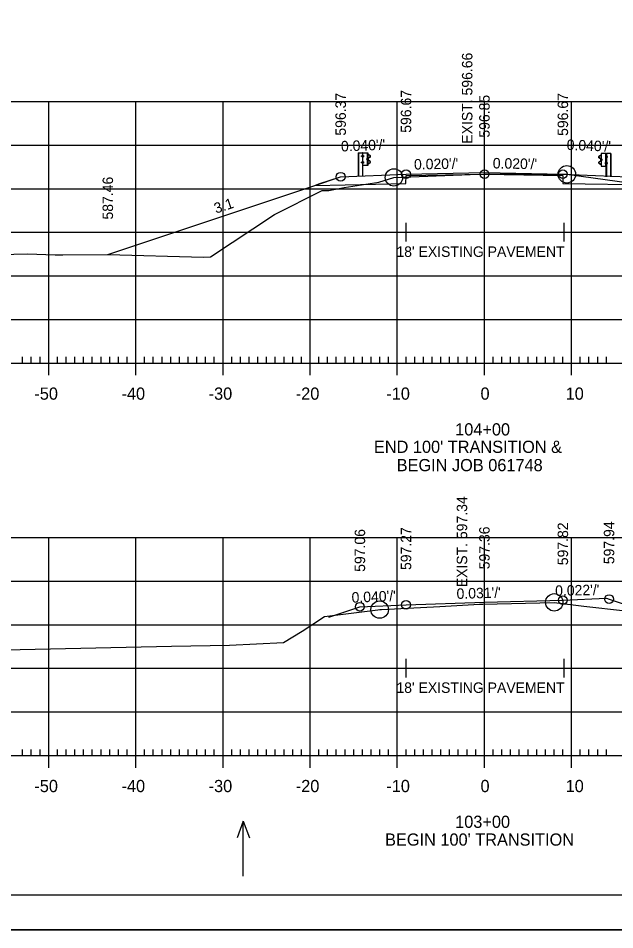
# Model space of a CAD drawing. Extents: x 961436 to 1372525, y 380079 to 2027791.
# Drawn here: x 1370137 to 1370205.5, y 380109.1 to 380213.6 of the extents above; entities that cross this region are included whole.
import ezdxf

# ---------------------------------------------------------------- set-up
doc = ezdxf.new("R2010")
doc.units = 0
for name, color, linetype in [('R_Alt Surface', 7, 'Continuous'), ('R_Axis', 7, 'Continuous'), ('R_Axis Annot', 7, 'Continuous'), ('R_Drive', 7, 'Continuous'), ('R_Exist Surface', 7, 'Continuous'), ('R_Fin Surface', 7, 'Continuous'), ('R_Fin Surface Annot', 7, 'Continuous'), ('R_Grid', 7, 'Continuous'), ('R_No Plot', 7, 'Continuous'), ('R_Proposed Road', 7, 'Continuous'), ('R_Water Annot', 7, 'Continuous'), ('R_Xsect Elev', 7, 'Continuous')]:
    doc.layers.add(name, color=color, linetype=linetype)

msp = doc.modelspace()

# ---------------------------------------------------------------- linework, layer by layer
at = {"layer": 'R_Alt Surface'}
msp.add_lwpolyline([(1370171.03, 380194.44), (1370181.49, 380194.65), (1370181.5, 380195.56), (1370190.5, 380195.74), (1370199.5, 380195.56), (1370199.51, 380194.65), (1370209.77, 380194.51)], dxfattribs=at)
at = {"layer": 'R_Axis'}
for p, q in [((1370137.5, 380174.06), (1370137.5, 380174.76)), ((1370138.5, 380174.06), (1370138.5, 380174.76)), ((1370139.5, 380174.06), (1370139.5, 380174.76)), ((1370140.5, 380172.66), (1370140.5, 380175.46)), ((1370141.5, 380174.06), (1370141.5, 380174.76)), ((1370142.5, 380174.06), (1370142.5, 380174.76)), ((1370143.5, 380174.06), (1370143.5, 380174.76)), ((1370144.5, 380174.06), (1370144.5, 380174.76)), ((1370145.5, 380174.06), (1370145.5, 380174.76)), ((1370146.5, 380174.06), (1370146.5, 380174.76)), ((1370147.5, 380174.06), (1370147.5, 380174.76)), ((1370148.5, 380174.06), (1370148.5, 380174.76)), ((1370149.5, 380174.06), (1370149.5, 380174.76)), ((1370150.5, 380172.66), (1370150.5, 380175.46)), ((1370151.5, 380174.06), (1370151.5, 380174.76)), ((1370152.5, 380174.06), (1370152.5, 380174.76)), ((1370153.5, 380174.06), (1370153.5, 380174.76)), ((1370154.5, 380174.06), (1370154.5, 380174.76)), ((1370155.5, 380174.06), (1370155.5, 380174.76)), ((1370156.5, 380174.06), (1370156.5, 380174.76)), ((1370157.5, 380174.06), (1370157.5, 380174.76)), ((1370158.5, 380174.06), (1370158.5, 380174.76)), ((1370159.5, 380174.06), (1370159.5, 380174.76)), ((1370160.5, 380172.66), (1370160.5, 380175.46)), ((1370161.5, 380174.06), (1370161.5, 380174.76)), ((1370162.5, 380174.06), (1370162.5, 380174.76)), ((1370163.5, 380174.06), (1370163.5, 380174.76)), ((1370164.5, 380174.06), (1370164.5, 380174.76)), ((1370165.5, 380174.06), (1370165.5, 380174.76)), ((1370166.5, 380174.06), (1370166.5, 380174.76)), ((1370167.5, 380174.06), (1370167.5, 380174.76)), ((1370168.5, 380174.06), (1370168.5, 380174.76)), ((1370169.5, 380174.06), (1370169.5, 380174.76)), ((1370170.5, 380172.66), (1370170.5, 380175.46)), ((1370171.5, 380174.06), (1370171.5, 380174.76)), ((1370172.5, 380174.06), (1370172.5, 380174.76)), ((1370173.5, 380174.06), (1370173.5, 380174.76)), ((1370174.5, 380174.06), (1370174.5, 380174.76)), ((1370175.5, 380174.06), (1370175.5, 380174.76)), ((1370176.5, 380174.06), (1370176.5, 380174.76)), ((1370177.5, 380174.06), (1370177.5, 380174.76)), ((1370178.5, 380174.06), (1370178.5, 380174.76)), ((1370179.5, 380174.06), (1370179.5, 380174.76)), ((1370180.5, 380172.66), (1370180.5, 380175.46)), ((1370181.5, 380174.06), (1370181.5, 380174.76)), ((1370182.5, 380174.06), (1370182.5, 380174.76)), ((1370183.5, 380174.06), (1370183.5, 380174.76)), ((1370184.5, 380174.06), (1370184.5, 380174.76)), ((1370185.5, 380174.06), (1370185.5, 380174.76)), ((1370186.5, 380174.06), (1370186.5, 380174.76)), ((1370187.5, 380174.06), (1370187.5, 380174.76)), ((1370188.5, 380174.06), (1370188.5, 380174.76)), ((1370189.5, 380174.06), (1370189.5, 380174.76)), ((1370190.5, 380172.66), (1370190.5, 380175.46)), ((1370191.5, 380174.06), (1370191.5, 380174.76)), ((1370192.5, 380174.06), (1370192.5, 380174.76)), ((1370193.5, 380174.06), (1370193.5, 380174.76)), ((1370194.5, 380174.06), (1370194.5, 380174.76)), ((1370195.5, 380174.06), (1370195.5, 380174.76)), ((1370196.5, 380174.06), (1370196.5, 380174.76)), ((1370197.5, 380174.06), (1370197.5, 380174.76)), ((1370198.5, 380174.06), (1370198.5, 380174.76)), ((1370199.5, 380174.06), (1370199.5, 380174.76)), ((1370200.5, 380172.66), (1370200.5, 380175.46)), ((1370201.5, 380174.06), (1370201.5, 380174.76)), ((1370202.5, 380174.06), (1370202.5, 380174.76)), ((1370203.5, 380174.06), (1370203.5, 380174.76)), ((1370204.5, 380174.06), (1370204.5, 380174.76)), ((1370050.5, 380174.06), (1370330.5, 380174.06)), ((1370137.5, 380129.06), (1370137.5, 380129.76)), ((1370138.5, 380129.06), (1370138.5, 380129.76)), ((1370139.5, 380129.06), (1370139.5, 380129.76)), ((1370140.5, 380127.66), (1370140.5, 380130.46)), ((1370141.5, 380129.06), (1370141.5, 380129.76)), ((1370142.5, 380129.06), (1370142.5, 380129.76)), ((1370143.5, 380129.06), (1370143.5, 380129.76)), ((1370144.5, 380129.06), (1370144.5, 380129.76)), ((1370145.5, 380129.06), (1370145.5, 380129.76)), ((1370146.5, 380129.06), (1370146.5, 380129.76)), ((1370147.5, 380129.06), (1370147.5, 380129.76)), ((1370148.5, 380129.06), (1370148.5, 380129.76)), ((1370149.5, 380129.06), (1370149.5, 380129.76)), ((1370150.5, 380127.66), (1370150.5, 380130.46)), ((1370151.5, 380129.06), (1370151.5, 380129.76)), ((1370152.5, 380129.06), (1370152.5, 380129.76)), ((1370153.5, 380129.06), (1370153.5, 380129.76)), ((1370154.5, 380129.06), (1370154.5, 380129.76)), ((1370155.5, 380129.06), (1370155.5, 380129.76)), ((1370156.5, 380129.06), (1370156.5, 380129.76)), ((1370157.5, 380129.06), (1370157.5, 380129.76)), ((1370158.5, 380129.06), (1370158.5, 380129.76)), ((1370159.5, 380129.06), (1370159.5, 380129.76)), ((1370160.5, 380127.66), (1370160.5, 380130.46)), ((1370161.5, 380129.06), (1370161.5, 380129.76)), ((1370162.5, 380129.06), (1370162.5, 380129.76)), ((1370163.5, 380129.06), (1370163.5, 380129.76)), ((1370164.5, 380129.06), (1370164.5, 380129.76)), ((1370165.5, 380129.06), (1370165.5, 380129.76)), ((1370166.5, 380129.06), (1370166.5, 380129.76)), ((1370167.5, 380129.06), (1370167.5, 380129.76)), ((1370168.5, 380129.06), (1370168.5, 380129.76)), ((1370169.5, 380129.06), (1370169.5, 380129.76)), ((1370170.5, 380127.66), (1370170.5, 380130.46)), ((1370171.5, 380129.06), (1370171.5, 380129.76)), ((1370172.5, 380129.06), (1370172.5, 380129.76)), ((1370173.5, 380129.06), (1370173.5, 380129.76)), ((1370174.5, 380129.06), (1370174.5, 380129.76)), ((1370175.5, 380129.06), (1370175.5, 380129.76)), ((1370176.5, 380129.06), (1370176.5, 380129.76)), ((1370177.5, 380129.06), (1370177.5, 380129.76)), ((1370178.5, 380129.06), (1370178.5, 380129.76)), ((1370179.5, 380129.06), (1370179.5, 380129.76)), ((1370180.5, 380127.66), (1370180.5, 380130.46)), ((1370181.5, 380129.06), (1370181.5, 380129.76)), ((1370182.5, 380129.06), (1370182.5, 380129.76)), ((1370183.5, 380129.06), (1370183.5, 380129.76)), ((1370184.5, 380129.06), (1370184.5, 380129.76)), ((1370185.5, 380129.06), (1370185.5, 380129.76)), ((1370186.5, 380129.06), (1370186.5, 380129.76)), ((1370187.5, 380129.06), (1370187.5, 380129.76)), ((1370188.5, 380129.06), (1370188.5, 380129.76)), ((1370189.5, 380129.06), (1370189.5, 380129.76)), ((1370190.5, 380127.66), (1370190.5, 380130.46)), ((1370191.5, 380129.06), (1370191.5, 380129.76)), ((1370192.5, 380129.06), (1370192.5, 380129.76)), ((1370193.5, 380129.06), (1370193.5, 380129.76)), ((1370194.5, 380129.06), (1370194.5, 380129.76)), ((1370195.5, 380129.06), (1370195.5, 380129.76)), ((1370196.5, 380129.06), (1370196.5, 380129.76)), ((1370197.5, 380129.06), (1370197.5, 380129.76)), ((1370198.5, 380129.06), (1370198.5, 380129.76)), ((1370199.5, 380129.06), (1370199.5, 380129.76)), ((1370200.5, 380127.66), (1370200.5, 380130.46)), ((1370201.5, 380129.06), (1370201.5, 380129.76)), ((1370202.5, 380129.06), (1370202.5, 380129.76)), ((1370203.5, 380129.06), (1370203.5, 380129.76)), ((1370204.5, 380129.06), (1370204.5, 380129.76)), ((1370050.5, 380129.06), (1370330.5, 380129.06))]:
    msp.add_line(p, q, dxfattribs=at)
at = {"layer": 'R_Drive'}
for p, q in [((1370181.49, 380190.13), (1370181.49, 380187.99)), ((1370199.62, 380190.13), (1370199.62, 380187.99)), ((1370181.49, 380189.06), (1370199.62, 380189.06)), ((1370181.49, 380140.13), (1370181.49, 380137.99)), ((1370199.62, 380140.13), (1370199.62, 380137.99)), ((1370181.49, 380139.06), (1370199.62, 380139.06))]:
    msp.add_line(p, q, dxfattribs=at)
at = {"layer": 'R_Exist Surface'}
for points in [[(1370127.01, 380186.32), (1370138.08, 380186.58), (1370141.22, 380186.47), (1370142.1, 380186.48), (1370147.29, 380186.52), (1370158.27, 380186.21), (1370159.05, 380186.26), (1370166.4, 380191.1), (1370171.89, 380193.84), (1370172.66, 380193.85), (1370174.4, 380194.18), (1370178.39, 380194.81), (1370180.11, 380195.35), (1370188.85, 380195.68), (1370190.52, 380195.72), (1370192.53, 380195.71), (1370199.96, 380195.71), (1370207.39, 380194.68)], [(1370129.95, 380141.09), (1370137.23, 380141.23), (1370154.6, 380141.59), (1370161.26, 380141.72), (1370167.44, 380142.01), (1370169.57, 380143.3), (1370172.15, 380145.01), (1370178.27, 380145.76), (1370178.48, 380145.79), (1370178.67, 380145.8), (1370185.4, 380146.16), (1370189.92, 380146.4), (1370190.32, 380146.41), (1370198.51, 380146.62), (1370201.9, 380146.2), (1370206.68, 380145.66), (1370207.43, 380145.38), (1370211.52, 380143.3), (1370217.62, 380140), (1370218.51, 380139.85), (1370218.93, 380139.84), (1370221.76, 380139.76), (1370248.2, 380139.15)]]:
    msp.add_lwpolyline(points, dxfattribs=at)
at = {"layer": 'R_Fin Surface'}
for points in [[(1370147.28, 380186.52), (1370171.03, 380194.44), (1370174, 380195.43), (1370181.5, 380195.73), (1370190.5, 380195.91), (1370199.5, 380195.73), (1370207, 380195.43), (1370209.77, 380194.51), (1370220.89, 380190.81), (1370235.05, 380186.08)], [(1370147.28, 380186.52), (1370171.03, 380194.44), (1370171.5, 380194.6), (1370174, 380195.43), (1370181.5, 380195.73), (1370190.5, 380195.91), (1370199.5, 380195.73), (1370207, 380195.43), (1370209.5, 380194.6), (1370209.98, 380194.44), (1370232.55, 380186.91), (1370235.05, 380186.08)], [(1370172.66, 380144.93), (1370173.32, 380145.15), (1370175.5, 380145.88), (1370176.21, 380146.12), (1370181.5, 380146.33), (1370190.5, 380146.65), (1370199.5, 380146.88), (1370204.5, 380147.09), (1370204.8, 380147), (1370208.95, 380145.61), (1370208.96, 380145.61), (1370213, 380144.27), (1370217.25, 380142.85), (1370226.86, 380139.64)]]:
    msp.add_lwpolyline(points, dxfattribs=at)
at = {"layer": 'R_Grid'}
for p, q in [((1370050.5, 380204.06), (1370330.5, 380204.06)), ((1370140.5, 380174.06), (1370140.5, 380204.06)), ((1370150.5, 380174.06), (1370150.5, 380204.06)), ((1370160.5, 380174.06), (1370160.5, 380204.06)), ((1370170.5, 380174.06), (1370170.5, 380204.06)), ((1370180.5, 380174.06), (1370180.5, 380204.06)), ((1370190.5, 380174.06), (1370190.5, 380204.06)), ((1370200.5, 380174.06), (1370200.5, 380204.06)), ((1370050.5, 380199.06), (1370330.5, 380199.06)), ((1370050.5, 380194.06), (1370330.5, 380194.06)), ((1370050.5, 380189.06), (1370330.5, 380189.06)), ((1370050.5, 380184.06), (1370330.5, 380184.06)), ((1370050.5, 380179.06), (1370330.5, 380179.06)), ((1370050.5, 380174.06), (1370330.5, 380174.06)), ((1370050.5, 380154.06), (1370330.5, 380154.06)), ((1370140.5, 380129.06), (1370140.5, 380154.06)), ((1370150.5, 380129.06), (1370150.5, 380154.06)), ((1370160.5, 380129.06), (1370160.5, 380154.06)), ((1370170.5, 380129.06), (1370170.5, 380154.06)), ((1370180.5, 380129.06), (1370180.5, 380154.06)), ((1370190.5, 380129.06), (1370190.5, 380154.06)), ((1370200.5, 380129.06), (1370200.5, 380154.06)), ((1370050.5, 380149.06), (1370330.5, 380149.06)), ((1370050.5, 380144.06), (1370330.5, 380144.06)), ((1370050.5, 380139.06), (1370330.5, 380139.06)), ((1370050.5, 380134.06), (1370330.5, 380134.06)), ((1370050.5, 380129.06), (1370330.5, 380129.06))]:
    msp.add_line(p, q, dxfattribs=at)
at = {"layer": 'R_No Plot'}
for p, q in [((1370348.68, 380113.06), (1370032.5, 380113.06)), ((1370020.1, 380109.08), (1370353.44, 380109.08))]:
    msp.add_line(p, q, dxfattribs=at)
for points in [[(1370020.1, 380322.41), (1370353.44, 380322.41), (1370353.44, 380109.08), (1370020.1, 380109.08)], [(1370266.42, 380318.52), (1370286.04, 380318.52), (1370286.04, 380308.64), (1370302.16, 380308.64), (1370325.36, 380308.64), (1370325.48, 380280.48), (1370348.68, 380280.48), (1370348.68, 380113.06), (1370032.5, 380113.06), (1370032.5, 380318.52)]]:
    msp.add_lwpolyline(points, close=True, dxfattribs=at)
for centre, radius in [((1370199.96, 380195.71), 1), ((1370174, 380195.43), 0.5), ((1370180.11, 380195.35), 1), ((1370181.5, 380195.73), 0.5), ((1370190.52, 380195.72), 0.5), ((1370199.5, 380195.73), 0.5), ((1370198.51, 380146.62), 1), ((1370199.5, 380146.88), 0.5), ((1370204.8, 380147), 0.5), ((1370176.21, 380146.12), 0.5), ((1370178.48, 380145.79), 1), ((1370181.5, 380146.33), 0.5)]:
    msp.add_circle(centre, radius, dxfattribs=at)
at = {"layer": 'R_Proposed Road'}
for p, q in [((1370176, 380198.18), (1370176, 380195.51)), ((1370176.04, 380198.18), (1370176.04, 380195.51)), ((1370176.43, 380197.74), (1370176.43, 380197.84)), ((1370176.49, 380197.73), (1370176.43, 380197.73)), ((1370176.49, 380197.86), (1370176.44, 380197.86)), ((1370176.49, 380197.83), (1370176.44, 380197.83)), ((1370176.49, 380197.76), (1370176.44, 380197.76)), ((1370176.49, 380197.76), (1370176.44, 380197.76)), ((1370176.56, 380198.18), (1370176.49, 380198.18)), ((1370176.49, 380197.73), (1370176.49, 380197.86)), ((1370176.53, 380195.51), (1370176.53, 380198.18)), ((1370176.56, 380198.18), (1370176.56, 380198.18)), ((1370176.62, 380197.79), (1370176.56, 380197.79)), ((1370176.57, 380197.85), (1370176.62, 380197.85)), ((1370176.57, 380197.72), (1370176.62, 380197.72)), ((1370176.62, 380197.85), (1370176.62, 380197.72)), ((1370177.02, 380197.4), (1370177.02, 380197.5)), ((1370177.08, 380197.52), (1370177.03, 380197.52)), ((1370177.08, 380197.39), (1370177.08, 380197.52)), ((1370177.09, 380196.73), (1370177.09, 380198.17)), ((1370177.24, 380197.95), (1370177.13, 380198.02)), ((1370177.23, 380197.93), (1370177.13, 380197.99)), ((1370177.13, 380197.39), (1370177.14, 380197.53)), ((1370177.16, 380197.39), (1370177.16, 380197.53)), ((1370177.18, 380197.6), (1370177.37, 380197.71)), ((1370177.2, 380197.58), (1370177.38, 380197.69)), ((1370177.37, 380197.82), (1370177.23, 380197.93)), ((1370177.38, 380197.84), (1370177.24, 380197.95)), ((1370203.63, 380197.76), (1370203.76, 380197.87)), ((1370203.81, 380197.5), (1370203.63, 380197.61)), ((1370203.64, 380197.74), (1370203.78, 380197.85)), ((1370203.83, 380197.52), (1370203.64, 380197.63)), ((1370203.76, 380197.87), (1370203.88, 380197.94)), ((1370203.78, 380197.85), (1370203.88, 380197.91)), ((1370203.92, 380196.65), (1370203.92, 380198.09)), ((1370204.44, 380197.77), (1370204.39, 380197.77)), ((1370204.39, 380197.77), (1370204.39, 380197.64)), ((1370204.39, 380197.71), (1370204.45, 380197.71)), ((1370204.44, 380197.64), (1370204.39, 380197.64)), ((1370204.45, 380198.1), (1370204.45, 380198.1)), ((1370204.45, 380198.1), (1370204.52, 380198.1)), ((1370204.48, 380195.43), (1370204.48, 380198.1)), ((1370204.52, 380197.65), (1370204.52, 380197.78)), ((1370204.52, 380197.78), (1370204.57, 380197.78)), ((1370204.52, 380197.75), (1370204.57, 380197.75)), ((1370204.52, 380197.68), (1370204.57, 380197.68)), ((1370204.52, 380197.68), (1370204.57, 380197.68)), ((1370204.52, 380197.65), (1370204.57, 380197.65)), ((1370204.58, 380197.66), (1370204.58, 380197.76)), ((1370204.97, 380198.1), (1370204.97, 380195.43)), ((1370205, 380198.1), (1370205, 380195.43)), ((1370176.42, 380197.01), (1370176.42, 380197.11)), ((1370176.48, 380197.1), (1370176.42, 380197.1)), ((1370176.48, 380197.03), (1370176.42, 380197.03)), ((1370176.48, 380197), (1370176.42, 380197)), ((1370176.48, 380197.13), (1370176.43, 380197.13)), ((1370176.48, 380197.03), (1370176.43, 380197.03)), ((1370176.48, 380197), (1370176.48, 380197.13)), ((1370176.56, 380196.73), (1370176.53, 380196.73)), ((1370176.62, 380197.06), (1370176.56, 380197.06)), ((1370176.62, 380197.13), (1370176.57, 380197.13)), ((1370176.62, 380197), (1370176.57, 380197)), ((1370176.62, 380197), (1370176.62, 380197.13)), ((1370177.08, 380197.49), (1370177.03, 380197.49)), ((1370177.08, 380197.42), (1370177.03, 380197.42)), ((1370177.08, 380197.42), (1370177.03, 380197.42)), ((1370177.08, 380197.39), (1370177.03, 380197.39)), ((1370177.12, 380196.9), (1370177.24, 380196.96)), ((1370177.13, 380196.88), (1370177.25, 380196.94)), ((1370177.34, 380197.2), (1370177.18, 380197.31)), ((1370177.36, 380197.23), (1370177.19, 380197.33)), ((1370177.24, 380196.96), (1370177.37, 380197.07)), ((1370177.25, 380196.94), (1370177.38, 380197.06)), ((1370203.76, 380196.86), (1370203.62, 380196.98)), ((1370203.77, 380196.88), (1370203.64, 380196.99)), ((1370203.65, 380197.15), (1370203.82, 380197.25)), ((1370203.67, 380197.12), (1370203.83, 380197.23)), ((1370203.88, 380196.8), (1370203.76, 380196.86)), ((1370203.89, 380196.82), (1370203.77, 380196.88)), ((1370203.85, 380197.31), (1370203.85, 380197.45)), ((1370203.88, 380197.31), (1370203.87, 380197.45)), ((1370203.93, 380197.31), (1370203.93, 380197.44)), ((1370203.93, 380197.44), (1370203.98, 380197.44)), ((1370203.93, 380197.41), (1370203.98, 380197.41)), ((1370203.93, 380197.34), (1370203.98, 380197.34)), ((1370203.93, 380197.34), (1370203.98, 380197.34)), ((1370203.93, 380197.31), (1370203.98, 380197.31)), ((1370203.99, 380197.32), (1370203.99, 380197.42)), ((1370204.39, 380196.92), (1370204.39, 380197.05)), ((1370204.39, 380197.05), (1370204.44, 380197.05)), ((1370204.39, 380196.98), (1370204.45, 380196.98)), ((1370204.39, 380196.92), (1370204.44, 380196.92)), ((1370204.45, 380196.65), (1370204.48, 380196.65)), ((1370204.53, 380196.92), (1370204.53, 380197.05)), ((1370204.53, 380197.05), (1370204.58, 380197.05)), ((1370204.53, 380197.02), (1370204.59, 380197.02)), ((1370204.53, 380196.95), (1370204.58, 380196.95)), ((1370204.53, 380196.95), (1370204.59, 380196.95)), ((1370204.53, 380196.92), (1370204.59, 380196.92)), ((1370204.59, 380196.93), (1370204.59, 380197.03))]:
    msp.add_line(p, q, dxfattribs=at)
for points in [[(1370176, 380198.18), (1370176.49, 380198.18), (1370176.49, 380195.51)], [(1370205, 380198.1), (1370204.52, 380198.1), (1370204.52, 380195.43)]]:
    msp.add_lwpolyline(points, dxfattribs=at)
for points in [[(1370176.43, 380197.83), (1370176.43, 380197.76), (1370176.4, 380197.76), (1370176.4, 380197.83)], [(1370176.49, 380197.88), (1370176.49, 380197.7), (1370176.5, 380197.7), (1370176.5, 380197.88)], [(1370177.12, 380198.18), (1370177.12, 380196.73), (1370176.56, 380196.73), (1370176.56, 380198.18)], [(1370176.62, 380197.85), (1370176.62, 380197.72), (1370176.56, 380197.72), (1370176.56, 380197.85)], [(1370177.08, 380197.54), (1370177.08, 380197.36), (1370177.09, 380197.36), (1370177.09, 380197.54)], [(1370203.89, 380198.1), (1370203.89, 380196.65), (1370204.45, 380196.65), (1370204.45, 380198.1)], [(1370204.39, 380197.77), (1370204.39, 380197.64), (1370204.45, 380197.64), (1370204.45, 380197.77)], [(1370204.52, 380197.8), (1370204.52, 380197.62), (1370204.51, 380197.62), (1370204.51, 380197.8)], [(1370204.58, 380197.75), (1370204.58, 380197.68), (1370204.61, 380197.68), (1370204.61, 380197.75)], [(1370176.42, 380197.1), (1370176.42, 380197.03), (1370176.39, 380197.03), (1370176.39, 380197.1)], [(1370176.48, 380197.15), (1370176.48, 380196.97), (1370176.49, 380196.97), (1370176.49, 380197.15)], [(1370176.62, 380197.13), (1370176.62, 380197), (1370176.56, 380197), (1370176.56, 380197.13)], [(1370177.02, 380197.49), (1370177.02, 380197.42), (1370176.99, 380197.42), (1370176.99, 380197.49)], [(1370203.93, 380197.46), (1370203.93, 380197.28), (1370203.92, 380197.28), (1370203.92, 380197.46)], [(1370203.99, 380197.41), (1370203.99, 380197.34), (1370204.02, 380197.34), (1370204.02, 380197.41)], [(1370204.39, 380197.05), (1370204.39, 380196.92), (1370204.45, 380196.92), (1370204.45, 380197.05)], [(1370204.53, 380197.07), (1370204.53, 380196.89), (1370204.52, 380196.89), (1370204.52, 380197.07)], [(1370204.59, 380197.02), (1370204.59, 380196.95), (1370204.62, 380196.95), (1370204.62, 380197.02)]]:
    msp.add_lwpolyline(points, close=True, dxfattribs=at)
for centre, radius, start, end in [((1370176.45, 380197.84), 0.0234, 134.5745, 222.2244), ((1370176.53, 380197.79), 0.0979, 159.7423, 200.2577), ((1370176.46, 380197.74), 0.0265, 140.9334, 216.6234), ((1370177.04, 380197.5), 0.0234, 134.5745, 222.2244), ((1370177.23, 380197.52), 0.0918, 118.106, 175.0444), ((1370177.23, 380197.52), 0.066, 118.106, 175.0444), ((1370177.15, 380197.45), 0.0481, 282.9554, 86.0697), ((1370177.33, 380197.77), 0.0658, 299.2499, 57.9783), ((1370177.33, 380197.77), 0.0909, 299.2499, 57.9783), ((1370203.68, 380197.69), 0.0909, 122.0217, 240.7501), ((1370203.68, 380197.69), 0.0658, 122.0217, 240.7501), ((1370203.78, 380197.44), 0.066, 4.9556, 61.894), ((1370203.78, 380197.44), 0.0918, 4.9556, 61.894), ((1370204.56, 380197.76), 0.0234, 317.7756, 45.4255), ((1370204.48, 380197.71), 0.0979, 339.7423, 20.2577), ((1370204.55, 380197.66), 0.0265, 323.3766, 39.0666), ((1370176.44, 380197.11), 0.0234, 134.5745, 222.2244), ((1370176.52, 380197.06), 0.0979, 159.7423, 200.2577), ((1370176.45, 380197.01), 0.0265, 140.9334, 216.6234), ((1370177.12, 380197.45), 0.0979, 159.7423, 200.2577), ((1370177.05, 380197.4), 0.0265, 140.9334, 216.6234), ((1370177.21, 380197.38), 0.0747, 171.7804, 246.8536), ((1370177.21, 380197.38), 0.049, 171.7804, 246.8536), ((1370177.3, 380197.13), 0.0907, 325.2184, 59.12), ((1370177.3, 380197.13), 0.116, 325.2184, 59.12), ((1370203.71, 380197.05), 0.116, 120.88, 214.7816), ((1370203.71, 380197.05), 0.0907, 120.88, 214.7816), ((1370203.86, 380197.37), 0.0481, 93.9303, 257.0446), ((1370203.8, 380197.3), 0.049, 293.1464, 8.2196), ((1370203.8, 380197.3), 0.0747, 293.1464, 8.2196), ((1370203.97, 380197.42), 0.0234, 317.7756, 45.4255), ((1370203.89, 380197.37), 0.0979, 339.7423, 20.2577), ((1370203.96, 380197.32), 0.0265, 323.3766, 39.0666), ((1370204.57, 380197.03), 0.0234, 317.7756, 45.4255), ((1370204.49, 380196.98), 0.0979, 339.7423, 20.2577), ((1370204.56, 380196.93), 0.0265, 323.3766, 39.0666)]:
    msp.add_arc(centre, radius, start, end, dxfattribs=at)
at = {"layer": 'R_Water Annot'}
for p, q in [((1370162.83, 380121.52), (1370162.13, 380119.6)), ((1370162.83, 380115.24), (1370162.83, 380121.52)), ((1370162.83, 380121.52), (1370163.53, 380119.6))]:
    msp.add_line(p, q, dxfattribs=at)

# ---------------------------------------------------------------- texts
at = {"layer": 'R_Axis Annot'}
for s, p in [('-50', (1370138.85, 380169.86)), ('-40', (1370148.85, 380169.86)), ('-30', (1370158.85, 380169.86)), ('-20', (1370168.85, 380169.86)), ('-10', (1370179.24, 380169.86)), ('0', (1370190.05, 380169.86)), ('10', (1370199.82, 380169.86)), ('104+00', (1370187.14, 380165.76)), ("END 100' TRANSITION & ", (1370177.82, 380163.76)), ('BEGIN JOB 061748', (1370180.43, 380161.66)), ('-50', (1370138.85, 380124.86)), ('-40', (1370148.85, 380124.86)), ('-30', (1370158.85, 380124.86)), ('-20', (1370168.85, 380124.86)), ('-10', (1370179.24, 380124.86)), ('0', (1370190.05, 380124.86)), ('10', (1370199.82, 380124.86)), ('103+00', (1370187.14, 380120.76)), ("BEGIN 100' TRANSITION", (1370179.1, 380118.72))]:
    msp.add_text(s, height=1.4, dxfattribs=at).set_placement(p)
at = {"layer": 'R_Fin Surface Annot'}
for s, rotation, p in [('596.37', 90, (1370174.6, 380200.14)), ('596.67', 90, (1370182.1, 380200.47)), ('596.67', 90, (1370200.1, 380200.11)), ('596.85', 90, (1370191.1, 380199.91)), ("0.040'/'", 2.2906, (1370174.06, 380198.32)), ("0.040'/'", 357.7094, (1370199.92, 380198.51)), ("0.020'/'", 1.1458, (1370182.43, 380196.25)), ("0.020'/'", 358.8542, (1370191.45, 380196.39)), ('587.46', 90, (1370147.88, 380190.52)), ('3:1', 18.4349, (1370159.7, 380191.19)), ('597.82', 90, (1370200.1, 380150.88)), ('597.94', 90, (1370205.4, 380151)), ('597.06', 90, (1370176.81, 380150.12)), ('597.27', 90, (1370182.1, 380150.33)), ('597.36', 90, (1370191.1, 380150.41)), ("0.031'/'", 1.7613, (1370187.32, 380147.01)), ("0.022'/'", 1.2317, (1370198.63, 380147.36)), ("0.040'/'", 2.2906, (1370175.28, 380146.58))]:
    msp.add_text(s, height=1.2, rotation=rotation, dxfattribs=at).set_placement(p)
for p in [(1370180.4, 380186.24), (1370180.4, 380136.24)]:
    msp.add_text("18' EXISTING PAVEMENT", height=1.2, dxfattribs=at).set_placement(p)
at = {"layer": 'R_Xsect Elev'}
for s, p in [('EXIST. 596.66', (1370189.12, 380199.22)), ('EXIST. 597.34', (1370188.52, 380148.35))]:
    msp.add_text(s, height=1.2, rotation=90, dxfattribs=at).set_placement(p)

doc.saveas('drawing.dxf')
